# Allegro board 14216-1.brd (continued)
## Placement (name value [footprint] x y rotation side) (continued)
R1202  -  [0R0402-PAD]  121.44 38.15 0 top
R1204  2MR2-GP  [R402H16]  92.28 13.4 90 top
R1205  -  [0R0402-PAD]  87.08 13.06 0 top
R1206  66D5R2F-GP  [R402H16]  92.24 18.05 90 top
R1207  66D5R2F-GP  [R402H16]  92.24 17.22 90 top
R1208  220KR2J-L2-GP  [R402H16]  92.28 14.29 270 top
R1209  66D5R2F-GP  [R402H16]  92.24 16.37 90 top
R1210  66D5R2F-GP  [R402H16]  92.24 15.52 90 top
R1301  -  [0R0402-PAD]  154.92 25.81 0 top
R1302  10KR2J-3-GP  [R402H16]  157.08 26.19 90 top
R1509  100KR2J-1-GP  [R402H16]  144.39 99.94 270 top
R1510  10KR2J-3-GP  [R402H16]  144.22 86.16 270 top
R1511  10KR2J-3-GP  [R402H16]  144.2 85.3 90 top
R1512  10KR2J-3-GP  [R402H16]  146.63 88.89 270 bottom
R1513  10KR2J-3-GP  [R402H16]  144.72 91.51 270 top
R1514  10KR2J-3-GP  [R402H16]  144.72 90.68 90 top
R1515  10KR2J-3-GP  [R402H16]  146.59 89.77 90 bottom
R1601  3KR2F-GP  [R402H16]  120.25 98.2 270 bottom
R1602  22D6R2F-L1-GP  [R402H16]  130.92 78.13 0 top
R1701  10KR2J-3-GP  [R402H16]  166.64 85.82 270 bottom
R1702  1KR2J-1-GP  [R402H16]  141.2 55.03 180 bottom
R1703  1KR2J-1-GP  [R402H16]  146.17 79.25 0 top
R1704  -  [0R0402-PAD]  142.23 56.44 90 bottom
R1705  0R2J-2-GP  [R402H16]  147.11 78.24 0 top
R1706  -  [0R0402-PAD]  140.53 56.44 270 bottom
R1707  -  [0R0402-PAD]  140.38 55.03 180 bottom
R1708  -  [0R0402-PAD]  160.77 67.53 180 bottom
R1709  -  [0R0402-PAD]  192.21 71.65 0 bottom
R1710  0R2J-2-GP  [R402H16]  150.73 83.72 270 bottom
R1713  -  [0R0402-PAD]  149.94 92.16 270 bottom
R1714  8K2R2F-1-GP  [R402H16]  192.22 69.93 180 bottom
R1715  100KR2J-1-GP  [R402H16]  149.83 93.91 90 bottom
R1717  10KR2J-3-GP  [R402H16]  171.04 82.71 270 bottom
R1718  0R2J-2-GP  [R402H16]  142.22 55.04 180 bottom
R1720  330KR2J-L1-GP  [R402H16]  139.84 64.39 0 top
R1721  330KR2J-L1-GP  [R402H16]  138.97 64.39 0 top
R1724  10KR2J-3-GP  [R402H16]  153.37 84.08 270 bottom
R1725  100KR2F-L1-GP  [R402H16]  143.02 53.67 90 bottom
R1726  10KR2J-3-GP  [R402H16]  159.21 49.25 270 bottom
R1727  100KR2J-1-GP  [R402H16]  159.19 48.4 90 bottom
R1728  -  [0R0402-PAD]  159.18 46.69 270 bottom
R1729  0R2J-2-GP  [R402H16]  159.19 47.55 270 bottom
R1801  -  [0R0402-PAD]  133.65 63.77 0 bottom
R1802  1MR2J-1-GP  [R402H16]  124.52 106.63 270 bottom
R1803  3KR2F-GP  [R402H16]  121.52 98.63 0 bottom
R1804  33R2J-2-GP  [R402H16]  129.39 64.42 0 top
R1805  33R2J-2-GP  [R402H16]  127.97 64.39 0 top
R1806  33R2J-2-GP  [R402H16]  144.17 83.04 90 bottom
R1807  -  [0R0402-PAD]  149.25 88.21 90 bottom
R1808  -  [0R0402-PAD]  144.18 83.87 90 bottom
R1809  -  [0R0402-PAD]  144.17 82.15 90 bottom
R1810  -  [0R0402-PAD]  122.82 106.63 90 bottom
R1811  -  [0R0402-PAD]  150.39 86.45 90 bottom
R1812  -  [0R0402-PAD]  143.88 80.48 90 bottom
R1813  0R2J-2-GP  [R402H16]  130.28 64.42 0 top
R1814  1KR2J-1-GP  [R402H16]  143.88 79.59 270 bottom
R1815  1KR2J-1-GP  [R402H16]  149.78 87.34 270 bottom
R1901  1MR2J-1-GP  [R402H16]  140.7 64.39 180 top
R1902  10KR2J-3-GP  [R402H16]  143.8 60.41 180 top
R1903  330KR2J-L1-GP  [R402H16]  140.37 63.12 0 bottom
R1904  -  [0R0402-PAD]  133.07 99.74 270 bottom
R1905  10KR2J-3-GP  [R402H16]  144.71 92.36 270 top
R1906  3KR2F-GP  [R402H16]  132.88 100.85 270 bottom
R1907  33R2J-2-GP  [R402H16]  138.4 64.38 0 bottom
R1908  -  [0R0402-PAD]  132.95 64.42 180 top
R1909  1KR2J-1-GP  [R402H16]  131.17 64.42 180 top
R1911  -  [0R0402-PAD]  139.22 64.38 0 bottom
R1912  33R2J-2-GP  [R402H16]  132.06 64.42 180 top
R1913  330KR2J-L1-GP  [R402H16]  141.21 63.14 0 bottom
R1915  10MR2J-L-GP  [R402H16]  148.62 67.34 180 bottom
R1916  51R2J-2-GP  [R402H16]  91.42 83.38 90 bottom
R1917  51R2J-2-GP  [R402H16]  91.42 80.08 90 bottom
R1918  51R2J-2-GP  [R402H16]  91.42 82.56 90 bottom
R1919  1KR2J-1-GP  [R402H16]  91.42 81.73 90 bottom
R1920  51R2J-2-GP  [R402H16]  91.43 80.9 270 bottom
R2001  -  [0R0402-PAD]  144.87 81.72 270 top
R2002  -  [0R0402-PAD]  144.89 80.87 270 top
R2003  49D9R2F-GP  [R402H16]  131.14 63.76 180 bottom
R2004  -  [0R0402-PAD]  144.28 87.87 270 top
R2005  10KR2J-3-GP  [R402H16]  144.2 85.63 90 bottom
R2006  1KR2J-1-GP  [R402H16]  144.21 88.26 90 bottom
R2007  100KR2J-1-GP  [R402H16]  144.2 87.41 270 bottom
R2008  10KR2J-3-GP  [R402H16]  144.2 84.74 270 bottom
R2009  -  [0R0402-PAD]  150.33 79.65 90 bottom
R2010  10KR2J-3-GP  [R402H16]  143.36 84.24 270 top
R2011  1KR2J-1-GP  [R402H16]  140.2 100.29 180 bottom
R2012  1KR2J-1-GP  [R402H16]  144.44 99.02 270 top
R2013  10KR2J-3-GP  [R402H16]  144.63 83.8 180 top
R2014  1KR2J-1-GP  [R402H16]  150.73 85.5 90 bottom
R2015  10KR2J-3-GP  [R402H16]  150.69 84.51 0 top
R2016  -  [0R0402-PAD]  144.86 82.54 270 top
R2017  -  [0R0402-PAD]  144.26 88.74 270 top
R2018  1KR2J-1-GP  [R402H16]  92.52 95.21 270 bottom
R2019  0R2J-2-GP  [R402H16]  149.96 86.71 0 top
R2020  -  [0R0402-PAD]  146.94 75.88 90 bottom
R2021  0R2J-2-GP  [R402H16]  150.28 81.55 90 top
R2022  -  [0R0402-PAD]  146.94 76.7 90 bottom
R2023  10KR2J-3-GP  [R402H16]  144.43 103.18 270 top
R2024  10KR2J-3-GP  [R402H16]  144.43 102.34 90 top
R2025  10KR2J-3-GP  [R402H16]  149.69 94.77 270 top
R2026  10KR2J-3-GP  [R402H16]  149.68 95.61 90 top
R2027  0R2J-2-GP  [R402H16]  92.51 96.05 90 bottom
R2028  -  [0R0402-PAD]  144.26 87.02 270 top
R2029  -  [0R0402-PAD]  144.26 89.59 270 top
R2030  0R2J-2-GP  [R402H16]  149.26 85.43 90 top
R2031  0R2J-2-GP  [R402H16]  150.7 82.81 0 top
R2032  10KR2J-3-GP  [R402H16]  152.82 79.24 270 bottom
R2033  10KR2J-3-GP  [R402H16]  143.11 103 0 top
R2034  10KR2J-3-GP  [R402H16]  142.22 103 180 top
R2035  10KR2J-3-GP  [R402H16]  148.19 76.33 0 bottom
R2101  -  [0R0402-PAD]  145.4 63.35 270 top
R2102  0R0603-PAD-1-GP-U  [0R0603-PAD-U]  124.51 72.63 90 top
R2103  -  [0R0402-PAD]  147.11 99.29 0 top
R2105  -  [0R0402-PAD]  139.04 106.59 180 bottom
R2108  0R0603-PAD-1-GP-U  [0R0603-PAD-U]  126.92 72.6 90 top
R2110  5D1R2F-GP  [R402H16]  125.08 80.14 270 top
R2112  -  [0R0402-PAD]  146.25 99.3 180 top
R2114  0R5J-5-GP  [R805H24]  146.1 111.36 180 bottom
R2117  -  [0R0402-PAD]  133.48 106.64 90 top
R2118  -  [0R0402-PAD]  127.19 104.6 270 top
R2122  0R0805-PAD-1-GP-U  [0R0805-PAD-U]  140.86 109.18 180 bottom
R2123  0R2J-2-GP  [R402H16]  144.2 86.52 270 bottom
R2401  -  [0R0402-PAD]  195.63 72.16 270 top
R2402  0R0603-PAD-1-GP-U  [0R0603-PAD-U]  180.8 61.9 90 top
R2403  2D2R3-1-U-GP  [R603H22]  183.23 61.49 270 top
R2404  10KR2F-2-GP  [R402H16]  179.12 62.98 270 top
R2405  0R2J-2-GP  [R402H16]  176.11 64.44 180 top
R2406  100KR2F-L1-GP  [R402H16]  178.21 64.9 270 top
R2407  100KR2F-L1-GP  [R402H16]  174.23 64.7 0 top
R2408  -  [0R0402-PAD]  195.42 83.62 270 bottom
R2409  -  [0R0402-PAD]  188.43 74.1 270 bottom
R2410  -  [0R0402-PAD]  189.46 64.92 0 top
R2411  0R2J-2-GP  [R402H16]  190.4 64.92 180 top
R2412  100KR2J-1-GP  [R402H16]  173.42 75.33 90 bottom
R2413  100KR2J-1-GP  [R402H16]  173.21 79.33 90 top
R2414  10KR2J-3-GP  [R402H16]  174.1 76.56 270 top
R2415  10KR2J-3-GP  [R402H16]  194.04 84.68 90 top
R2416  -  [0R0402-PAD]  187.08 70.95 90 bottom
R2417  -  [0R0402-PAD]  194.79 80.88 0 top
R2418  10KR2J-3-GP  [R402H16]  174.6 73.36 180 top
R2419  33R2J-2-GP  [R402H16]  173.31 69.52 90 top
R2420  33R2J-2-GP  [R402H16]  173.31 68.64 90 top
R2421  100KR2J-1-GP  [R402H16]  185.43 66.94 0 bottom
R2422  33R2J-2-GP  [R402H16]  172.93 71.25 90 top
R2423  33R2J-2-GP  [R402H16]  172.93 72.08 90 top
R2424  0R2J-2-GP  [R402H16]  172.9 73.36 0 top
R2425  330KR2J-L1-GP  [R402H16]  173.87 67.8 270 top
R2426  100KR2J-1-GP  [R402H16]  189.86 70.4 180 bottom
R2427  -  [0R0402-PAD]  173.87 66.91 90 top
R2428  -  [0R0402-PAD]  185.7 63.63 0 top
R2429  43R2J-GP  [R402H16]  196.07 67.9 0 top
R2430  -  [0R0402-PAD]  173.21 78.47 90 top
R2431  330KR2J-L1-GP  [R402H16]  169.17 73.38 90 bottom
R2432  1KR2J-1-GP  [R402H16]  171.29 73.81 180 bottom
R2433  20KR2F-L-GP  [R402H16]  170.47 73.81 0 bottom
R2434  0R2J-2-GP  [R402H16]  180.71 60.8 270 top
R2435  -  [0R0402-PAD]  181.6 65.11 270 top
R2436  10KR2J-3-GP  [R402H16]  195.1 75.49 270 top
R2437  0R2J-2-GP  [R402H16]  177.29 85.26 270 bottom
R2438  0R2J-2-GP  [R402H16]  176.48 70.8 0 bottom
R2439  10KR2J-3-GP  [R402H16]  169.88 64.11 180 top
R2440  -  [0R0402-PAD]  176.81 72.59 0 bottom
R2441  -  [0R0402-PAD]  173.16 77.55 270 top
R2442  100KR2J-1-GP  [R402H16]  177.77 71.31 270 bottom
R2443  10KR2J-3-GP  [R402H16]  191.09 66.48 270 bottom
R2444  -  [0R0402-PAD]  194.6 67.8 180 top
R2446  64K9R2F-1-GP  [R402H16]  173.95 66.04 90 top
R2447  100KR2J-1-GP  [R402H16]  195.08 70.78 270 top
R2448  0R2J-2-GP  [R402H16]  188.27 64.67 180 top
R2449  1KR2J-1-GP  [R402H16]  175.39 81.65 180 top
R2450  0R2J-2-GP  [R402H16]  189.87 72.11 180 bottom
R2451  0R2J-2-GP  [R402H16]  184.86 63.63 180 top
R2452  1KR2J-1-GP  [R402H16]  182.06 83 90 bottom
R2453  1KR2J-1-GP  [R402H16]  183.82 82.99 270 bottom
R2501  4K7R2J-2-GP  [R402H16]  156.12 55.02 270 bottom
R2502  1KR2J-1-GP  [R402H16]  33.32 14.73 90 top
R2504  10MR2J-L-GP  [R402H16]  33.32 13.84 90 top
R2601  0R2J-2-GP  [R402H16]  126.42 116.7 270 bottom
R2602  0R2J-2-GP  [R402H16]  128.15 116.68 270 bottom
R2603  18K7R2F-GP  [R402H16]  132.15 115.69 0 bottom
R2604  2KR2F-3-GP  [R402H16]  124.71 116.69 270 bottom
R2605  0R2J-2-GP  [R402H16]  95.31 143.7 270 bottom
R2606  -  [0R0402-PAD]  96.15 140.19 90 bottom
R2607  2KR2F-3-GP  [R402H16]  129.88 116.71 90 bottom
R2608  24K9R2F-L-GP  [R402H16]  133.61 111.5 90 bottom
R2609  24K9R2F-L-GP  [R402H16]  133.62 112.34 90 bottom
R2610  NTC-100K-8-GP  [NTC-603H38]  133.51 114.22 270 bottom
R2611  -  [0R0402-PAD]  182.42 63.54 270 top
R2612  -  [0R0402-PAD]  167.06 64.93 90 top
R2701  -  [0R0402-PAD]  177.23 22.8 270 bottom
R2702  0R0805-PAD-1-GP-U  [0R0805-PAD-U]  176.71 11.06 270 bottom
R2703  0R0603-PAD-1-GP-U  [0R0603-PAD-U]  193.14 19.77 270 bottom
R2704  0R0805-PAD-1-GP-U  [0R0805-PAD-U]  176.7 9.24 270 bottom
R2705  -  [0R0402-PAD]  188.64 9.56 0 bottom
R2706  0R0805-PAD-1-GP-U  [0R0805-PAD-U]  192.34 11.1 270 bottom
R2707  20KR2F-L-GP  [R402H16]  181.59 22.13 0 bottom
R2708  -  [0R0402-PAD]  181.46 13.11 270 top
R2709  200KR2F-L-GP  [R402H16]  180.45 22.13 0 bottom
R2710  0R2J-2-GP  [R402H16]  187.75 9.55 0 bottom
R2711  100KR2J-1-GP  [R402H16]  189.21 19.42 90 bottom
R2712  -  [0R0402-PAD]  183.64 29.62 0 bottom
R2714  -  [0R0402-PAD]  177.48 13.24 270 bottom
R2716  -  [0R0402-PAD]  177.53 14.13 270 bottom
R2717  1KR2J-1-GP  [R402H16]  175.51 21.91 90 bottom
R2718  -  [0R0402-PAD]  176.77 18.77 270 bottom
R2719  -  [0R0402-PAD]  176.36 15.52 270 bottom
R2720  -  [0R0402-PAD]  177.45 16.34 270 bottom
R2722  100KR2J-1-GP  [R402H16]  178.43 21.95 270 bottom
R2901  0R0603-PAD-1-GP-U  [0R0603-PAD-U]  88.6 5.06 90 top
R2902  0R0603-PAD-1-GP-U  [0R0603-PAD-U]  88.48 6.58 90 top
R2903  0R0603-PAD-1-GP-U  [0R0603-PAD-U]  88.48 8.74 90 top
R2904  0R0603-PAD-1-GP-U  [0R0603-PAD-U]  88.48 10.65 90 top
R2906  0R0603-PAD-1-GP-U  [0R0603-PAD-U]  184.26 22.13 270 top
R2907  0R0603-PAD-1-GP-U  [0R0603-PAD-U]  184 28.1 270 top
R2908  10R2F-L-GP  [R402H14]  188.98 15.22 270 bottom
R2909  0R0603-PAD-1-GP-U  [0R0603-PAD-U]  184 26.7 270 top
R2910  10R2F-L-GP  [R402H14]  192.13 15.52 270 bottom
R2911  0R0603-PAD-1-GP-U  [0R0603-PAD-U]  184.26 23.52 270 top
R2912  4K7R2J-2-GP  [R402H16]  189.87 16.11 270 bottom
R2913  4K7R2J-2-GP  [R402H16]  192.13 17.3 270 bottom
R2919  10KR2J-3-GP  [R402H16]  182.23 28.73 180 top
R2920  10KR2J-3-GP  [R402H16]  182.23 27 180 top
R2921  1KR2J-1-GP  [R402H16]  191.58 24.08 270 bottom
R2922  1KR2J-1-GP  [R402H16]  191.54 23.03 270 bottom
R2923  0R0603-PAD-1-GP-U  [0R0603-PAD-U]  180.45 24.29 180 bottom
R3001  0R3J-0-U-GP  [R603H22]  55.52 174.61 180 top
R3003  10KR2J-3-GP  [R402H16]  47.01 162.98 0 top
R3004  10KR2J-3-GP  [R402H16]  53.22 163.06 0 top
R3005  -  [0R0402-PAD]  52.37 163.06 0 top
R3006  0R0603-PAD-1-GP-U  [0R0603-PAD-U]  54.96 172.08 270 top
R3014  1KR2J-1-GP  [R402H16]  54.24 167.85 270 top
R3015  15KR2J-1-GP  [R402H16]  54.24 166.98 90 top
R3016  -  [0R0402-PAD]  58.57 168.07 270 top
R3021  10KR2J-3-GP  [R402H16]  62.7 173.06 90 top
R3022  20KR2J-L2-GP  [R402H16]  62.7 172.18 270 top
R3023  100KR2J-1-GP  [R402H16]  59.07 169.78 270 top
R3032  2K49R2F-GP  [R402H16]  45.07 172.88 90 top
R3033  10KR2J-3-GP  [R402H16]  54.25 168.72 90 top
R3201  33R2J-2-GP  [R402H16]  19.97 19.18 270 bottom
R3202  -  [0R0402-PAD]  15.76 22.59 90 bottom
R3203  6K2R2F-GP  [R402H16]  14 12.5 180 bottom
R3204  -  [0R0402-PAD]  12.18 12.18 0 bottom
R3205  -  [0R0402-PAD]  11.17 12.18 0 bottom
R3301  -  [0R0402-PAD]  29.55 26.3 270 top
R3408  -  [0R0402-PAD]  24.01 40.64 270 bottom
R3409  -  [0R0402-PAD]  24.14 39.62 270 bottom
R3410  -  [0R0402-PAD]  23.3 38.1 270 bottom
R3411  -  [0R0402-PAD]  23.3 37.08 270 bottom
R3501  0R2J-2-GP  [R402H16]  147.92 78.23 180 top
R3601  1KR2J-1-GP  [R402H16]  133.66 143.44 180 top
R3602  200KR2F-L-GP  [R402H16]  162.47 62.72 0 top
R3603  1KR2J-1-GP  [R402H16]  162.49 64.42 180 top
R3605  2K2R2J-2-GP  [R402H16]  164.88 67.59 270 top
R3606  4K7R2J-2-GP  [R402H16]  164.88 66.76 270 top
R3607  100KR2J-1-GP  [R402H16]  28.63 17.66 180 top
R3608  1KR2J-1-GP  [R402H16]  164.88 65.77 270 top
R3609  -  [0R0402-PAD]  39.25 21.49 0 top
R3610  -  [0R0402-PAD]  134.51 143.44 180 top
R3611  -  [0R0402-PAD]  134.1 144.65 270 bottom
R3701  1K8R2F-GP  [R402H16]  59.8 51.85 0 top
R3702  2R2F-GP  [R402H16]  61.96 51.46 270 top
R3703  1K8R2F-GP  [R402H16]  65.01 51.46 270 top
R3704  0R2J-2-GP  [R402H16]  65.01 50.58 90 top
R3705  -  [0R0402-PAD]  66.78 50.7 90 top
R3706  1K8R2F-GP  [R402H16]  66.78 51.59 270 top
R3707  24D9R2F-L-GP  [R402H16]  63.74 51.85 0 top
R3708  2R2F-GP  [R402H16]  65.01 52.35 270 top
R3709  1K8R2F-GP  [R402H16]  61.96 50.58 90 top
R3710  0R2J-2-GP  [R402H16]  59.42 50.45 90 top
R3711  24D9R2F-L-GP  [R402H16]  61.2 53.24 270 top
R3712  0R2J-2-GP  [R402H16]  58.53 51.34 270 top
R3713  2R2F-GP  [R402H16]  58.15 53.7 0 top
R3714  1K8R2F-GP  [R402H16]  59.42 53.24 90 top
R3715  24D9R2F-L-GP  [R402H16]  57.28 53.67 0 top
R3716  1K8R2F-GP  [R402H16]  58.53 52.35 270 top
R3801  0R0805-PAD-1-GP-U  [0R0805-PAD-U]  181.06 71.51 90 bottom
R3802  0R2J-2-GP  [R402H16]  147.46 77.6 270 bottom
R4301  -  [0R0402-PAD]  156.98 174.94 180 top
R4622  2KR2F-3-GP  [R402H16]  118.66 145.83 90 top
R5201  -  [0R0402-PAD]  76.33 164.67 90 bottom
R5202  100KR2J-1-GP  [R402H16]  80.5 154.59 180 bottom
R5203  -  [0R0402-PAD]  85.15 158.25 90 top
R5204  -  [0R0402-PAD]  85.15 157.24 90 top
R5205  33R2J-2-GP  [R402H16]  84.84 155.39 90 top
R5206  -  [0R0402-PAD]  69.32 164.11 90 bottom
R5207  33R2J-2-GP  [R402H16]  81.31 164.44 180 top
R5208  10KR2J-3-GP  [R402H16]  73.79 165.79 0 bottom
R5209  0R2J-2-GP  [R402H16]  74.68 165.79 180 bottom
R5210  100R2J-2-GP  [R402H14]  76.33 165.5 90 bottom
R5211  0R5J-5-GP  [R805H24]  80.42 159.49 180 bottom
R5212  100R2J-2-GP  [R402H14]  84.85 154.55 90 top
R5213  100R2J-2-GP  [R402H14]  85.05 177.31 270 bottom
R5214  0R5J-5-GP  [R805H24]  95.87 154.64 90 bottom
R5215  33R2J-2-GP  [R402H16]  82.19 164.44 180 top
R5216  -  [0R0402-PAD]  84.2 160.88 90 top
R5217  -  [0R0402-PAD]  84.21 160.02 90 top
R5218  100KR2J-1-GP  [R402H16]  81.31 173.51 180 top
R5219  100KR2J-1-GP  [R402H16]  81.31 171.81 0 top
R5222  0R2J-2-GP  [R402H16]  68.03 164.55 180 bottom
R5229  0R5J-5-GP  [R805H24]  85.55 158.53 0 bottom
R5230  0R3J-0-U-GP  [R603H22]  76.05 157 0 bottom
R5231  0R3J-0-U-GP  [R603H22]  77.71 157 0 bottom
R5232  0R3J-0-U-GP  [R603H22]  76.44 160.94 180 bottom
R5401  -  [0R0402-PAD]  21.09 77.96 90 bottom
R5402  -  [0R0402-PAD]  21.09 77.07 90 bottom
R5403  -  [0R0402-PAD]  20.81 75.82 90 bottom
R5404  -  [0R0402-PAD]  20.81 74.99 90 bottom
R5405  -  [0R0402-PAD]  20 68.47 180 bottom
R5406  -  [0R0402-PAD]  20.89 68.47 180 bottom
R5407  -  [0R0402-PAD]  20.76 73.66 90 bottom
R5408  -  [0R0402-PAD]  20.76 72.8 90 bottom
R5409  0R0603-PAD-1-GP-U  [0R0603-PAD-U]  31.93 70.5 90 bottom
R5410  200KR2F-L-GP  [R402H16]  19.82 79.07 270 bottom
R5411  150KR2F-L-GP  [R402H16]  19.82 79.96 270 bottom
R5412  10KR2J-3-GP  [R402H16]  30.69 77.58 270 bottom
R5413  100KR2J-1-GP  [R402H16]  35.05 70.17 270 bottom
R5414  150R2J-L1-GP-U  [R402H16]  19.11 77.47 180 bottom
R5415  150R2J-L1-GP-U  [R402H16]  20.45 66.41 270 bottom
R5416  150R2J-L1-GP-U  [R402H16]  18.8 75.67 180 bottom
R5417  150R2J-L1-GP-U  [R402H16]  18.8 73.94 180 bottom
R5418  0R2J-2-GP  [R402H16]  25.56 79.07 0 top
R5419  -  [0R0402-PAD]  30.69 78.44 90 bottom
R5501  75R2F-2-GP  [R402H16]  23.72 63.9 0 top
R5502  4K7R2J-2-GP  [R402H16]  28.32 59.09 180 bottom
R5503  0R3J-0-U-GP  [R603H22]  23.52 67.37 90 top
R5504  0R3J-0-U-GP  [R603H22]  30.59 59.06 90 top
R5505  12KR2F-L-GP  [R402H16]  31.37 64.77 0 bottom
R5507  33R2J-2-GP  [R402H16]  26.45 68.83 180 top
R5508  4K7R2J-2-GP  [R402H16]  29.67 61.31 180 bottom
R5509  4K7R2J-2-GP  [R402H16]  29.67 59.06 180 bottom
R5510  100KR2J-1-GP  [R402H16]  31.17 68.49 180 top
R5511  33R2J-2-GP  [R402H16]  25.59 68.84 180 top
R5512  4K7R2J-2-GP  [R402H16]  28.84 61.31 180 bottom
R5513  75R2F-2-GP  [R402H16]  23.69 61.64 0 top
R5514  75R2F-2-GP  [R402H16]  23.63 58.92 0 top
R5515  4K7R2J-2-GP  [R402H16]  30.5 59.06 180 bottom
R5516  4K7R2J-2-GP  [R402H16]  30.51 61.31 180 bottom
R5517  0R2J-2-GP  [R402H16]  32.01 68.48 180 top
R5601  0R0805-PAD-1-GP-U  [0R0805-PAD-U]  191.68 38.97 180 bottom
R5602  0R2J-2-GP  [R402H16]  153.58 88.2 0 bottom
R5603  0R5J-5-GP  [R805H24]  158.92 78.98 90 bottom
R5604  10KR2J-3-GP  [R402H16]  151.52 90.05 180 top
R5605  -  [0R0402-PAD]  148.78 96.6 270 bottom
R5607  100KR2J-1-GP  [R402H16]  162.62 73.46 90 bottom
R5801  -  [0R0402-PAD]  158.78 63.28 0 bottom
R5802  -  [0R0402-PAD]  159.79 63.28 0 bottom
R5803  -  [0R0402-PAD]  163.05 53.07 180 top
R5804  -  [0R0402-PAD]  177.9 53.65 0 top
R5805  -  [0R0402-PAD]  178.73 53.65 0 top
R5806  0R2J-2-GP  [R402H16]  177.42 55.7 270 top
R5807  -  [0R0402-PAD]  177.01 53.65 0 top
R5808  -  [0R0402-PAD]  158.69 55.21 0 bottom
R5809  0R0805-PAD-1-GP-U  [0R0805-PAD-U]  166.73 38.44 180 top
R5810  0R2J-2-GP  [R402H16]  169.45 38.49 180 top
R5811  -  [0R0402-PAD]  159.68 55.21 0 bottom
R6102  100R2J-2-GP  [R402H14]  191.19 173.35 90 top
R6103  470R2J-2-GP  [R402H16]  30.18 4.54 90 top
R6104  -  [0R0402-PAD]  36 9.2 270 top
R6105  -  [0R0402-PAD]  32.72 9.2 270 top
R6106  0R2J-2-GP  [R402H16]  44.18 3.71 270 top
R6107  330R2J-3-GP  [R402H16]  33.98 4.53 90 top
R6108  330R2J-3-GP  [R402H16]  37.83 3.71 270 top
R6109  100R2J-2-GP  [R402H14]  191.58 176.34 180 top
R6110  10KR2J-3-GP  [R402H16]  42.76 8.71 270 top
R6201  1KR2J-1-GP  [R402H16]  194.61 117.39 270 top
R6202  -  [0R0402-PAD]  196.47 112.79 270 top
R6203  10KR2J-3-GP  [R402H16]  59.9 75.87 180 bottom
R6204  0R2J-2-GP  [R402H16]  47.4 74.31 90 top
R6205  0R3J-0-U-GP  [R603H22]  186.11 122.44 90 top
R6206  51KR2J-1-GP  [R402H16]  186.92 123.93 180 top
R6207  100KR2J-1-GP  [R402H16]  186.03 123.93 180 top
R6208  100KR2J-1-GP  [R402H16]  189.97 127.72 0 top
R6209  4K7R2J-2-GP  [R402H16]  58.52 71.79 0 top
R6210  0R2J-2-GP  [R402H16]  47.4 73.47 90 top
R6211  100R3J-4-GP  [R603H22]  48.15 69.88 270 top
R6212  0R3J-0-U-GP  [R603H22]  50.42 79.12 0 top
R6213  0R3J-0-U-GP  [R603H22]  48.19 75.93 90 top
R6214  20KR2F-L-GP  [R402H16]  45.08 79.16 90 top
R6215  0R2J-2-GP  [R402H16]  47.41 77.46 0 bottom
R6216  -  [0R0402-PAD]  43.68 79.85 270 bottom
R6217  0R2J-2-GP  [R402H16]  48.25 77.46 0 bottom
R6301  0R2J-2-GP  [R402H16]  187.89 35.11 90 top
R6302  0R2J-2-GP  [R402H16]  187.89 31.04 90 top
R6305  0R3J-0-U-GP  [R603H22]  192.28 12.67 270 bottom
R6501  0R2J-2-GP  [R402H16]  169.78 35.41 90 bottom
R6502  0R2J-2-GP  [R402H16]  168.49 35.84 180 bottom
R7301  2K49R2F-GP  [R402H16]  151.6 150 90 bottom
R7302  10KR2F-2-GP  [R402H16]  151.72 142.5 90 bottom
R7303  10KR2J-3-GP  [R402H16]  148.41 130.26 90 bottom
R7304  0R2J-2-GP  [R402H16]  151.36 121.76 180 bottom
R7305  0R2J-2-GP  [R402H16]  151.39 126.84 270 bottom
R7306  100KR2F-L1-GP  [R402H16]  152.22 121.76 0 bottom
R7307  200R2F-L-GP  [R402H16]  152.13 144.3 180 bottom
R7308  0R2J-2-GP  [R402H16]  157.52 125.2 90 bottom
R7312  10KR2J-3-GP  [R402H16]  158.8 125.64 180 bottom
R7313  0R2J-2-GP  [R402H16]  190.51 126.1 180 bottom
R7501  60D4R2F-GP  [R402H16]  171.94 145.65 270 top
R7503  60D4R2F-GP  [R402H16]  169.58 146.49 270 top
R7505  40D2R2F-GP  [R402H16]  175.63 146.06 0 top
R7506  51D1R2F-GP  [R402H16]  177.94 151.84 270 top
R7507  42D2R2F-GP  [R402H16]  176.49 148.24 270 top
R7508  10KR2F-2-GP  [R402H16]  183.39 161.58 90 bottom
R7509  10KR2F-2-GP  [R402H16]  151.75 163.61 270 top
R7510  10KR2F-2-GP  [R402H16]  199.19 142.27 180 bottom
R7511  10KR2F-2-GP  [R402H16]  166.13 164.04 180 bottom
R7512  10KR2F-2-GP  [R402H16]  198.3 142.27 180 bottom
R7518  10KR2J-3-GP  [R402H16]  171.25 130.32 180 top
R7519  0R2J-2-GP  [R402H16]  172.64 129.92 90 top
R7601  10KR2J-3-GP  [R402H16]  193.79 129.05 90 bottom
R7602  10KR2J-3-GP  [R402H16]  172.53 139.51 180 top
R7603  1MR2J-1-GP  [R402H16]  180.19 129.44 180 bottom
R7604  1K3R2J-GP  [R402H16]  180.19 127.66 0 bottom
R7605  100KR2J-1-GP  [R402H16]  174.02 128.47 270 top
R7606  10KR2J-3-GP  [R402H16]  174.86 130.08 180 top
R7607  40K2R2F-GP  [R402H16]  171.94 133 90 top
R7608  4K99R2F-L-GP  [R402H16]  187.43 130 90 top
R7609  10KR2J-3-GP  [R402H16]  170.42 123.91 90 bottom
R7610  100KR2J-1-GP  [R402H16]  188.53 129.47 180 bottom
R7611  4K99R2F-L-GP  [R402H16]  192.38 128.56 0 bottom
R7612  10KR2J-3-GP  [R402H16]  196.99 123.95 180 bottom
R7613  10KR2J-3-GP  [R402H16]  191.4 126.1 0 bottom
R7614  10KR2F-2-GP  [R402H16]  187.43 129.19 270 top
R7615  10KR2J-3-GP  [R402H16]  171.69 123.68 0 bottom
R7616  20KR2F-L-GP  [R402H16]  191.12 129.57 180 top
R7617  10KR2J-3-GP  [R402H16]  172.77 137.22 90 top
R7618  10KR2F-2-GP  [R402H16]  190.3 129.57 0 top
R7619  34K8R2F-1-GP  [R402H16]  191.55 128.56 0 bottom
R7620  10KR2F-2-GP  [R402H16]  194.13 127.74 180 bottom
R7621  10KR2J-3-GP  [R402H16]  173.86 125.53 180 bottom
R7622  10KR2J-3-GP  [R402H16]  173.77 124.27 270 bottom
R7623  0R2J-2-GP  [R402H16]  195.54 129.98 90 bottom
R7624  -  [0R0402-PAD]  200.26 136.79 90 top
R7625  10KR2J-3-GP  [R402H16]  175.59 125.53 0 bottom
R7626  10KR2J-3-GP  [R402H16]  180.58 129.7 90 top
R7627  10KR2J-3-GP  [R402H16]  195.51 129.12 270 bottom
R7628  10KR2J-3-GP  [R402H16]  175.5 137.45 0 top
R7629  0R2J-2-GP  [R402H16]  186.67 127.16 180 bottom
R7630  0R2J-2-GP  [R402H16]  176.64 130.08 0 top
R7631  10KR2J-3-GP  [R402H16]  175.75 130.08 180 top
R7632  10KR2J-3-GP  [R402H16]  176.86 125.33 270 bottom
R7633  10KR2J-3-GP  [R402H16]  179.18 125.43 270 bottom
R7634  10KR2J-3-GP  [R402H16]  176 124.16 270 bottom
R7635  10KR2J-3-GP  [R402H16]  172.5 123.68 0 bottom
R7636  0R2J-2-GP  [R402H16]  180.47 124.59 180 bottom
R7637  10KR2J-3-GP  [R402H16]  174.73 131.86 180 top
R7638  30K1R2F-L-GP  [R402H16]  193.56 129.57 180 top
R7639  24K9R2F-L-GP  [R402H16]  192.74 129.57 180 top
R7640  4K99R2F-L-GP  [R402H16]  191.93 129.57 180 top
R7642  30K1R2F-L-GP  [R402H16]  190.35 129.44 180 bottom
R7643  10KR2J-3-GP  [R402H16]  187.56 127.16 180 bottom
R7644  10KR2J-3-GP  [R402H16]  181.36 124.59 0 bottom
R7645  10KR2J-3-GP  [R402H16]  188.45 127.16 0 bottom
R7646  45K3R2F-L-GP  [R402H16]  174.75 125.53 0 bottom
R7647  34K8R2F-1-GP  [R402H16]  173.77 123.45 270 bottom
R7648  10KR2J-3-GP  [R402H16]  145.87 130.65 180 top
R7649  10KR2J-3-GP  [R402H16]  182.66 124.88 270 bottom
R7650  4K99R2F-L-GP  [R402H16]  170.42 124.72 90 bottom
R7652  -  [0R0402-PAD]  187.64 129.47 0 bottom
R7653  -  [0R0402-PAD]  193.82 122.1 270 bottom
R7654  45K3R2F-L-GP  [R402H16]  176.87 126.17 270 bottom
R7655  45K3R2F-L-GP  [R402H16]  189.47 129.44 180 bottom
R7806  1K33R2F-GP  [R402H16]  198.3 134.96 90 bottom
R7807  1K33R2F-GP  [R402H16]  198.31 133.2 270 bottom
R7808  243R2F-2-GP  [R402H16]  193.02 129.98 90 bottom
R7809  243R2F-2-GP  [R402H16]  186.54 143.86 90 bottom
R7810  162R2F-GP  [R402H16]  188.37 143.9 270 top
R7903  1K33R2F-GP  [R402H16]  152.18 165.81 0 top
R7904  1K33R2F-GP  [R402H16]  180.83 165.64 270 bottom
R7912  243R2F-2-GP  [R402H16]  180.83 164.75 90 bottom
R7913  243R2F-2-GP  [R402H16]  166.22 162.34 180 bottom
R7914  162R2F-GP  [R402H16]  166.25 162.25 0 top
R8001  243R2F-2-GP  [R402H16]  189.95 158.28 0 top
R8002  243R2F-2-GP  [R402H16]  186.65 143.89 270 top
R8101  243R2F-2-GP  [R402H16]  151.75 164.49 90 top
R8102  243R2F-2-GP  [R402H16]  166.26 160.54 180 top
R8301  100KR2J-1-GP  [R402H16]  145.83 128.91 0 top
R8302  10KR2J-3-GP  [R402H16]  144.37 132.27 270 top
R8303  0R2J-2-GP  [R402H16]  142.68 132.28 270 top
R8304  0R5J-5-GP  [R805H24]  182.89 124.47 270 top
R8305  1MR2J-1-GP  [R402H16]  166.86 57.05 180 top
R8312  0R2J-2-GP  [R402H16]  168.15 56.32 270 top
R8313  0R2J-2-GP  [R402H16]  142.96 138.6 90 top
R8314  220KR2J-L2-GP  [R402H16]  171.53 56.37 270 top
R8315  0R2J-2-GP  [R402H16]  179.18 124.54 270 bottom
R9601  1KR2J-1-GP  [R402H16]  100.52 100.27 270 top
R9602  0R2J-2-GP  [R402H16]  149.86 95.71 270 bottom
R9603  0R2J-2-GP  [R402H16]  187.71 69.5 180 bottom
R9604  0R2J-2-GP  [R402H16]  90.02 88.93 270 bottom
R9605  0R2J-2-GP  [R402H16]  171.01 84.46 270 bottom
RJ45  RJ45-8P-184-GP  [C100PF-10809-L]  6.4 170.97 90 bottom
RN401  SRN51J-1-GP  [ARES8-CN24H22]  88.24 90.92 270 bottom
RN1501  SRN2K2J-1-GP  [ARES2H16]  135.26 99.89 0 bottom
RN1503  SRN10KJ-5-GP  [ARES2H18]  150.19 89.87 270 bottom
RN1505  SRN10KJ-6-GP  [ARES8-CN24-MUH20]  144.56 97.08 270 bottom
RN1601  SRN10KJ-6-GP  [ARES8-CN24-MUH20]  153.45 76.2 270 bottom
RN1701  SRN10KJ-5-GP  [ARES2H18]  168.86 82.46 180 top
RN1702  SRN0J-6-GP  [SMD-ARES4H20]  162.73 67.59 270 bottom
RN1703  SRN10KJ-5-GP  [ARES2H18]  141.16 57.99 90 bottom
RN1801  SRN10KJ-6-GP  [ARES8-CN24-MUH20]  144.54 93.4 270 bottom
RN1803  SRN10KJ-5-GP  [ARES2H18]  112.36 99.5 0 bottom
RN1804  SRN10KJ-5-GP  [ARES2H18]  137.5 63.71 0 top
RN1806  SRN0J-7-GP-U  [ARES8-CN24H22]  135.46 63.58 0 bottom
RN1807  SRN2K2J-4-GP  [ARES8-CN24-UH20]  158.99 72.46 90 bottom
RN1809  SRN10KJ-6-GP  [ARES8-CN24-MUH20]  151.11 81.82 270 bottom
RN1810  SRN10KJ-5-GP  [ARES2H18]  161.78 70.39 0 bottom
RN1811  SRN2K2J-1-GP  [ARES2H16]  158.03 69.23 270 bottom
RN1901  SRN20KJ-1-GP  [SMD-ARES4H20]  142.36 62.44 0 top
RN1902  SRN10KJ-6-GP  [ARES8-CN24-MUH20]  144.34 90.49 90 bottom
RN2002  SRN10KJ-6-GP  [ARES8-CN24-MUH20]  144.57 94.2 90 top
RN2006  SRN10KJ-5-GP  [ARES2H18]  166.79 81.66 180 top
RN2007  SRN10KJ-5-GP  [ARES2H18]  141.73 101.06 180 bottom
RN2008  SRN2K2J-1-GP  [ARES2H16]  143.76 101.06 180 bottom
RN2011  SRN10KJ-6-GP  [ARES8-CN24-MUH20]  144.57 97.12 90 top
RN2012  SRN10KJ-6-GP  [ARES8-CN24-MUH20]  153.48 82.25 90 bottom
RN2401  SRN4K7J-8-GP  [SMD-ARES4H18]  174.21 85.11 180 bottom
RN2501  SRN4K7J-8-GP  [SMD-ARES4H18]  150.45 55.66 270 bottom
RN2602  SRN2K2J-1-GP  [ARES2H16]  126.98 118.83 270 top
RN2701  -  [0R4P2R-PAD]  176.17 27.74 270 bottom
RN2901  SRN2K2J-1-GP  [ARES2H16]  181.13 22.72 270 top
RN3001  SRN10KJ-5-GP  [ARES2H18]  58.05 162.98 270 top
RN3101  SRN75J-1-GP  [ARES8-CN24H22]  21.7 177.58 180 bottom
RN4301  SRN100J-4-GP  [ARES8-CN24H20]  161.99 175.08 90 top
RN4401  SRN4K7J-8-GP  [SMD-ARES4H18]  101.98 160.91 90 bottom
RN5201  SRN100J-4-GP  [ARES8-CN24H20]  76.18 167.34 270 bottom
RN5203  SRN100KJ-5-GP  [ARES8-CN24H20]  71.66 167.34 90 bottom
RN5401  SRN2K2J-1-GP  [ARES2H16]  36.99 78.92 90 bottom
RN5402  SRN470J-3-GP  [ARES8-CN24H20]  24.37 72.67 90 top
RN5403  SRN470J-3-GP  [ARES8-CN24H20]  24.37 76.61 90 top
RN5404  -  [0R4P2R-PAD]  38.46 75.41 270 bottom
RN5405  -  [0R4P2R-PAD]  38.46 73.36 270 bottom
RN5501  SRN2K2J-1-GP  [ARES2H16]  28.56 70.49 0 top
RN6201  SRN10KJ-5-GP  [ARES2H18]  52.64 77.75 270 top
RN6202  SRN33J-5-GP-U  [SMD-ARES4H18]  56.7 77.64 270 top
RN6203  SRN33J-5-GP-U  [SMD-ARES4H18]  49.82 73.88 90 top
RN6204  SRN2K2J-1-GP  [ARES2H16]  56.65 74.17 180 top
RN6501  SRN0J-7-GP-U  [ARES8-CN24H22]  172.02 36.04 0 bottom
RN7401  SRN10KJ-5-GP  [ARES2H18]  163.93 131.67 0 top
RN7402  SRN10KJ-5-GP  [ARES2H18]  161.9 131.67 0 top
RN7403  SRN10KJ-5-GP  [ARES2H18]  170.67 134.9 90 top
RN7404  SRN10KJ-5-GP  [ARES2H18]  165.96 131.67 0 top
RN7501  SRN100J-3-GP  [SMD-ARES4H18]  190.85 167.6 180 bottom
RN7502  SRN100J-3-GP  [SMD-ARES4H18]  190.62 164.31 90 bottom
RN7503  SRN100J-3-GP  [SMD-ARES4H18]  180.73 165.51 0 top
RN7504  SRN100J-3-GP  [SMD-ARES4H18]  180.71 159.13 0 top
RN7505  SRN100J-3-GP  [SMD-ARES4H18]  185.83 166.27 0 top
RN7506  SRN100J-3-GP  [SMD-ARES4H18]  188.79 167.61 180 bottom
RN7507  SRN100J-3-GP  [SMD-ARES4H18]  187.84 167.08 0 top
RN7508  SRN100J-3-GP  [SMD-ARES4H18]  190.4 166.54 270 top
RN7509  SRN100J-3-GP  [SMD-ARES4H18]  190.4 168.56 270 top
RN7510  SRN100J-3-GP  [SMD-ARES4H18]  190.7 162.27 90 bottom
RN7511  SRN100J-3-GP  [SMD-ARES4H18]  182.76 164.19 0 top
RN7512  SRN100J-3-GP  [SMD-ARES4H18]  183.45 169.39 0 top
RN7513  SRN100J-3-GP  [SMD-ARES4H18]  187.97 158.44 270 top
RN7514  SRN100J-3-GP  [SMD-ARES4H18]  187.97 160.47 270 top
RN7515  SRN100J-3-GP  [SMD-ARES4H18]  180.74 162.44 0 top
RN7516  SRN100J-3-GP  [SMD-ARES4H18]  181.41 169.39 0 top
RN7517  SRN100J-3-GP  [SMD-ARES4H18]  185.8 169.35 0 top
RN7518  SRN100J-3-GP  [SMD-ARES4H18]  190.42 162.48 270 top
RN7519  SRN100J-3-GP  [SMD-ARES4H18]  191.04 160.47 270 top
RN7520  SRN100J-3-GP  [SMD-ARES4H18]  186.69 167.6 180 bottom
RN7521  SRN100J-3-GP  [SMD-ARES4H18]  190.42 164.49 270 top
RN7522  SRN100J-3-GP  [SMD-ARES4H18]  183.28 166.73 90 top
RN7601  SRN4K7J-8-GP  [SMD-ARES4H18]  199.37 135.28 270 top
RN7602  SRN10KJ-5-GP  [ARES2H18]  150.86 130.84 90 bottom
RN7603  SRN2K2J-1-GP  [ARES2H16]  180.45 126.39 0 top
RN7604  SRN2K2J-1-GP  [ARES2H16]  199.37 133.13 90 top
RN7605  SRN2K2J-1-GP  [ARES2H16]  178.42 126.39 0 top
RN9601  SRN0J-6-GP  [SMD-ARES4H20]  163.81 70.39 180 bottom
RTC1  BAT-060003HA002M213ZL-GP-U1  [060003HA002M213ZL-U2]  41.3 14.77 180 bottom
SPI25  W25Q64FVSSIQ-GP  [SOIC8-1H86]  152.13 51.29 270 bottom
SPK1  ACES-CON4-29-GP  [50224-0040N-001]  72.1 7.22 270 bottom
SPR1  SPRING-31-GP  [SPR7345H154]  85.3 59.27 270 top
SPR2  SPRING-24-GP-U  [SPR5230H134]  69.8 77.57 0 bottom
SPR3  SPRING-13-GP-U  [SPR7837H229]  134.3 35.02 90 bottom
TC1201  ST330U2VDM-4-GP-U  [CT7343H83]  73.26 40.92 270 top
TC3501  SC100U6D3V6MX-GP  [C1206H71]  21.57 42.31 0 top
THM26  NCT7718W-GP  [MSOP8-1H44]  128.38 114.2 90 bottom
TP402  TPAD14-OP-GP  [TPAD14-OP]  95.07 89.15 180 bottom
TP403  TPAD14-OP-GP  [TPAD14-OP]  94.37 97.41 180 bottom
TP501  TPAD14-OP-GP  [TPAD14-OP]  117.41 76.91 0 top
TP503  TPAD14-OP-GP  [TPAD14-OP]  118.39 78.74 0 top
TP601  TPAD14-OP-GP  [TPAD14-OP]  95.05 72.98 180 bottom
TP602  TPAD14-OP-GP  [TPAD14-OP]  97.9 72.55 0 top
TP603  TPAD14-OP-GP  [TPAD14-OP]  98.1 94.94 0 top
TP604  TPAD14-OP-GP  [TPAD14-OP]  98.06 96.91 0 top
TP605  TPAD14-OP-GP  [TPAD14-OP]  110.65 95.71 0 top
TP606  TPAD14-OP-GP  [TPAD14-OP]  106.92 96.8 0 top
TP607  TPAD14-OP-GP  [TPAD14-OP]  106.92 94.9 0 top
TP608  TPAD14-OP-GP  [TPAD14-OP]  98.35 89.02 0 top
TP619  TPAD14-OP-GP  [TPAD14-OP]  125.94 86.62 0 top
TP620  TPAD14-OP-GP  [TPAD14-OP]  126.91 87.51 0 top
TP701  TPAD14-OP-GP  [TPAD14-OP]  99.8 98.58 180 bottom
TP702  TPAD14-OP-GP  [TPAD14-OP]  102.11 87.09 0 top
TP703  TPAD14-OP-GP  [TPAD14-OP]  101.39 86.03 0 top
TP704  TPAD14-OP-GP  [TPAD14-OP]  102.07 88.33 0 top
TP705  TPAD14-OP-GP  [TPAD14-OP]  100.32 86.92 0 top
TP801  TPAD14-OP-GP  [TPAD14-OP]  111.31 96.83 0 top
TP1501  TPAD14-OP-GP  [TPAD14-OP]  135.39 82.11 0 top
TP1601  TPAD14-OP-GP  [TPAD14-OP]  131.88 76.61 0 top
TP1602  TPAD14-OP-GP  [TPAD14-OP]  131.88 74.73 0 top
TP1702  TPAD14-OP-GP  [TPAD14-OP]  137.01 80.29 0 top
TP1703  TPAD14-OP-GP  [TPAD14-OP]  135.39 76.21 0 top
TP1704  TPAD14-OP-GP  [TPAD14-OP]  135.23 79.1 0 top
TP1705  TPAD14-OP-GP  [TPAD14-OP]  133.03 77.89 0 top
TP1706  TPAD14-OP-GP  [TPAD14-OP]  140.52 80.32 180 bottom
TP1707  TPAD14-OP-GP  [TPAD14-OP]  133.73 80.17 0 top
TP1801  TPAD14-OP-GP  [TPAD14-OP]  140.89 81.49 180 bottom
TP1802  TPAD14-OP-GP  [TPAD14-OP]  142.09 82.8 180 bottom
TP1803  TPAD14-OP-GP  [TPAD14-OP]  141.72 80.59 180 bottom
TP1901  TPAD14-OP-GP  [TPAD14-OP]  96.88 71.78 0 top
TP1902  TPAD14-OP-GP  [TPAD14-OP]  137.38 64.89 180 bottom
TP2002  TPAD14-OP-GP  [TPAD14-OP]  138.92 76.99 0 top
TP2003  TPAD14-OP-GP  [TPAD14-OP]  135.7 91.43 0 top
TP2101  TPAD14-OP-GP  [TPAD14-OP]  127.72 86.59 0 top
TP2102  TPAD14-OP-GP  [TPAD14-OP]  127.86 85.16 0 top
TP2103  TPAD14-OP-GP  [TPAD14-OP]  127.13 89.35 0 top
TP2104  TPAD14-OP-GP  [TPAD14-OP]  125.76 87.96 0 top
TP2105  TPAD14-OP-GP  [TPAD14-OP]  129.05 85.76 0 top
TP2106  TPAD14-OP-GP  [TPAD14-OP]  133.05 82.1 0 top
TP2107  TPAD14-OP-GP  [TPAD14-OP]  130.15 89.42 0 top
TP2108  TPAD14-OP-GP  [TPAD14-OP]  129.3 78.4 0 top
TP2109  TPAD14-OP-GP  [TPAD14-OP]  132.29 83.06 0 top
TP2201  TPAD14-OP-GP  [TPAD14-OP]  97.29 67.62 180 bottom
TP2202  TPAD14-OP-GP  [TPAD14-OP]  138.23 99.27 180 bottom
TP2203  TPAD14-OP-GP  [TPAD14-OP]  94.22 98.66 180 bottom
TP2204  TPAD14-OP-GP  [TPAD14-OP]  140.02 98.41 180 bottom
TP2205  TPAD14-OP-GP  [TPAD14-OP]  98.07 98.25 0 top
TP2206  TPAD14-OP-GP  [TPAD14-OP]  140.53 73.51 180 bottom
TP2207  TPAD14-OP-GP  [TPAD14-OP]  140.5 72.25 180 bottom
TP2208  TPAD14-OP-GP  [TPAD14-OP]  95.94 69.09 180 bottom
TP2702  TPAD14-OP-GP  [TPAD14-OP]  179.56 12.73 270 top
TP3001  TPAD14-OP-GP  [TPAD14-OP]  51.74 177.3 0 top
TP3002  TPAD14-OP-GP  [TPAD14-OP]  50.9 178.2 180 top
TP3003  TPAD14-OP-GP  [TPAD14-OP]  49.96 172.65 180 top
TP3201  TPAD14-OP-GP  [TPAD14-OP]  19.77 16.83 180 bottom
TP5801  TPAD14-OP-GP  [TPAD14-OP]  159.57 52.13 0 top
TP5802  TPAD14-OP-GP  [TPAD14-OP]  168.41 51.19 0 top
TP5803  TPAD14-OP-GP  [TPAD14-OP]  167.13 51.17 0 top
TP5804  TPAD14-OP-GP  [TPAD14-OP]  165.75 51.17 0 top
TP7503  TPAD14-OP-GP  [TPAD14-OP]  172.55 144.61 0 top
TP7504  TPAD14-OP-GP  [TPAD14-OP]  170.8 152.43 0 top
TP7601  TPAD14-OP-GP  [TPAD14-OP]  155.56 133.15 0 top
TP7602  TPAD14-OP-GP  [TPAD14-OP]  158.1 134.52 0 top
TP7603  TPAD14-OP-GP  [TPAD14-OP]  177.75 137.21 0 top
TP7604  TPAD14-OP-GP  [TPAD14-OP]  176.53 137.2 0 top
TP7605  TPAD14-OP-GP  [TPAD14-OP]  157.21 133.38 0 top
TP7606  TPAD14-OP-GP  [TPAD14-OP]  189.47 125.63 180 bottom
TP9601  TPAD14-OP-GP  [TPAD14-OP]  96.91 89.67 0 top
TP9602  TPAD14-OP-GP  [TPAD14-OP]  97.54 90.94 0 top
TP9611  TPAD14-OP-GP  [TPAD14-OP]  89.97 91.78 180 bottom
TP9612  TPAD14-OP-GP  [TPAD14-OP]  96.27 90.94 0 top
TP9613  TPAD14-OP-GP  [TPAD14-OP]  99.95 91.2 0 top
TP9614  TPAD14-OP-GP  [TPAD14-OP]  93.73 90.05 180 bottom
TP9615  TPAD14-OP-GP  [TPAD14-OP]  95.1 90.38 180 bottom
TP9616  TPAD14-OP-GP  [TPAD14-OP]  101.53 90.4 0 top
TP9617  TPAD14-OP-GP  [TPAD14-OP]  92.46 90.05 180 bottom
TP9618  TPAD14-OP-GP  [TPAD14-OP]  100.26 89.64 0 top
TP9619  TPAD14-OP-GP  [TPAD14-OP]  98.86 90.15 0 top
TP9620  TPAD14-OP-GP  [TPAD14-OP]  96.4 82.69 0 top
TP9621  TPAD14-OP-GP  [TPAD14-OP]  101.33 92.49 0 top
TP9622  TPAD14-OP-GP  [TPAD14-OP]  93.93 84.38 180 bottom
TP9623  TPAD14-OP-GP  [TPAD14-OP]  91.83 91.32 180 bottom
TP9624  TPAD14-OP-GP  [TPAD14-OP]  89.98 90.46 180 bottom
TP9626  TPAD14-OP-GP  [TPAD14-OP]  101.22 83.7 0 top
TP9627  TPAD14-OP-GP  [TPAD14-OP]  97.67 82.69 0 top
TP9628  TPAD14-OP-GP  [TPAD14-OP]  96.69 84.61 0 top
TP9629  TPAD14-OP-GP  [TPAD14-OP]  99.95 83.78 0 top
TP9630  TPAD14-OP-GP  [TPAD14-OP]  98.68 83.58 0 top
TP9631  TPAD14-OP-GP  [TPAD14-OP]  97.98 84.73 0 top
TP9632  TPAD14-OP-GP  [TPAD14-OP]  94.51 85.97 0 top
TP9633  TPAD14-OP-GP  [TPAD14-OP]  93.58 84.9 0 top
TP9634  TPAD14-OP-GP  [TPAD14-OP]  95.21 83.19 0 top
TP9635  TPAD14-OP-GP  [TPAD14-OP]  94.02 83.56 0 top
TP9636  TPAD14-OP-GP  [TPAD14-OP]  95.2 84.92 0 top
TP9637  TPAD14-OP-GP  [TPAD14-OP]  100.47 85.12 0 top
TP9638  TPAD14-OP-GP  [TPAD14-OP]  95.76 86.03 0 top
TP9639  TPAD14-OP-GP  [TPAD14-OP]  97.01 86.08 0 top
TP9640  TPAD14-OP-GP  [TPAD14-OP]  96.14 87.89 0 top
TP9641  TPAD14-OP-GP  [TPAD14-OP]  99.31 85.49 0 top
TP9642  TPAD14-OP-GP  [TPAD14-OP]  97.41 87.89 0 top
TP9643  TPAD14-OP-GP  [TPAD14-OP]  94.87 87.89 0 top
TP9644  TPAD14-OP-GP  [TPAD14-OP]  171.43 85.55 0 bottom
TP9645  TPAD14-OP-GP  [TPAD14-OP]  186.52 68.78 180 bottom
TP9646  TPAD14-OP-GP  [TPAD14-OP]  167.19 73.41 180 bottom
TP9647  TPAD14-OP-GP  [TPAD14-OP]  91.17 90.07 180 bottom
TP9648  TPAD14-OP-GP  [TPAD14-OP]  99.97 101.59 0 top
TP9649  TPAD14-OP-GP  [TPAD14-OP]  165.97 73.5 180 bottom
TP9650  TPAD14-OP-GP  [TPAD14-OP]  98.42 93.75 0 top
TP9651  TPAD14-OP-GP  [TPAD14-OP]  114 99.97 180 bottom
TP9652  TPAD14-OP-GP  [TPAD14-OP]  114.03 98.74 180 bottom
TP9653  TPAD14-OP-GP  [TPAD14-OP]  140.43 82.97 180 bottom
TP9654  TPAD14-OP-GP  [TPAD14-OP]  147.53 95.69 180 bottom
TPAD1  ACES-CON8-40-GP  [50505-0084N-002]  66.3 77.27 90 top
TR3404  FILTER-4P-137-GP  [L125100-4P-1H28]  21.93 35 0 top
TR3405  FILTER-4P-137-GP  [L125100-4P-1H28]  183.96 40.67 180 bottom
TR3406  FILTER-4P-137-GP  [L125100-4P-1H28]  183.33 36.88 180 bottom
U701  74LVC1G07GW-GP  [SC70-5H44]  100.24 96.96 180 top
U2101  SLG59M1470VTR-GP  [DFN9J2015H32]  143.43 111.74 270 bottom
U3201  RTS5170-GR-GP  [QFN24-G2D5H40-U]  16.03 17.58 270 bottom
U3402  AZ1045-04F-R7G-GP  [DFN10G2510H26]  19.26 39.68 270 bottom
U3504  AP22802BW5-7-GP  [SOT-23-5H58]  26.27 45.34 90 bottom
U3505  AP22802BW5-7-GP  [SOT-23-5H58]  198.69 19.08 0 bottom
U3601  AP22966DC8-7-GP  [SON14J3020-G2610H32]  39.28 17.94 0 top
U3801  SY6288C10CAC-GP  [MSOP8-1H44]  181.52 68.5 270 bottom
U5201  RT9724GB-GP  [SOT-23-5H51]  83.29 154.97 90 bottom
U5502  RTD2168-CGT-GP  [QFN32-G3D6H40]  28.39 63.83 0 top
U5504  CAT24C128WI-GT3-GP  [SOIC8H69]  28.25 51.9 180 bottom
U5601  TPS2001CDGNR-GP  [MSOP8-1G189157H43]  159.84 75.97 270 bottom
U7301  U74LVC1G08G-AL5-R-GP-U  [SC70-5-1H44]  149.37 122.94 0 bottom
U8301  AP22966DC8-7-GP  [SON14J3020-G2610H32]  147.43 137.32 90 top
USB1  SKT-USB13-111-GP  [SKT-USB13-160166-2]  5.27 39.97 90 bottom
VRAM1  MT41K256M16HA-107G-E-GP  [BGA96D0914H48]  188.4 136.92 270 bottom
VRAM2  MT41K256M16HA-107G-E-GP  [BGA96D0914H48]  188.4 150.91 270 bottom
VRAM3  MT41K256M16HA-107G-E-GP  [BGA96D0914H48]  173.2 162.37 0 bottom
VRAM4  MT41K256M16HA-107G-E-GP  [BGA96D0914H48]  159.2 162.37 0 bottom
VRAM5  MT41K256M16HA-107G-E-GP  [BGA96D0914H48]  188.4 136.92 90 top
VRAM6  MT41K256M16HA-107G-E-GP  [BGA96D0914H48]  188.4 150.91 90 top
VRAM7  MT41K256M16HA-107G-E-GP  [BGA96D0914H48]  173.2 162.37 180 top
VRAM8  MT41K256M16HA-107G-E-GP  [BGA96D0914H48]  159.2 162.37 180 top
WLAN1  SKT-MINI67P-3-GP-U1  [2199230-7]  168.6 53.77 90 bottom
X1801  XTAL-24MHZ-81-GP  [OSC-3225-4P-4H36]  124.26 109.94 0 bottom
X1901  XTAL-32D768KHZ-65-GP  [SMD49-6914-0403H56]  154.63 66.26 0 bottom
X3001  XTAL-25MHZ-181-GP  [OSC-3225-4P-4H36]  47.83 176.61 180 top
X7601  XTAL-27MHZ-85-GP-U  [OSC-3225-4P-4H30]  183.88 128.55 0 bottom
XF3101  XFORM-12P-48-GP  [XFORM12A127097H91]  24.21 168.94 90 bottom
XF3102  XFORM-12P-48-GP  [XFORM12A127097H91]  24.21 168.94 270 top

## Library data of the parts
AFTP2501 AFTP2502 AFTP2801-AFTP2803 AFTP2901-AFTP2904 AFTP3101-AFTP3108 AFTP3301-AFTP3310 AFTP3401-AFTP3403 AFTP3801-AFTP3803 AFTP3805 AFTP3806 AFTP3901-AFTP3910 AFTP5501-AFTP5508 AFTP5601 AFTP5801-AFTP5807 AFTP6101-AFTP6104 AFTP6201-AFTP6203 AFTP6206-AFTP6208 AFTP6213-AFTP6243 AFTP6245-AFTP6248 AFTP6301-AFTP6307 AFTP6309-AFTP6311 AFTP6313 AFTP6314 = AFTE14P-75: tolerance: ZZ.AFT14.101
BATT1 = 200277MR008G121ZR-U: tolerance: 20.81153.008
C701 C3512 C3513 C3515 C7326 C7518 C7520 C7710 C7717 PC4717-PC4737 PC4739-PC4742 PC4744 PC4923-PC4928 = C805H58: tolerance: 78.22610.51L
C702 C1120 C1121 C1201-C1204 C1206 C1210 C1211 C1217 C1218 C1220-C1222 C1301 C1302 C1306 C1308-C1311 C1314 C1316 C1317 C1319 C1320 C2110 C2136 C2147 C2401-C2404 C2406-C2410 C2412 C2414 C2417 C2502 C2602 C2605 C2608-C2610 C2612 C2707 C2709 C2710 C2717 C2719 C2720 C3002 C3003 C3007-C3009 C3013 C3017 C3019 C3021-C3025 C3202 C3205 C3301 C3405 C3406 C3504 C3507 C3517 C3604 C5201 C5401 C5501 C5503 C5517 C5520 C5522 C5524 C5604 C5606 C5801-C5804 C6201-C6204 C7318 C7501 C7502 C7505 C7506 C7508-C7510 C7512 C7522-C7524 C7529 C7532-C7534 C7601 C7602 C7605 C7729 C7734 C7735 C7804 C7820 C7821 C7827 C7829-C7836 C7909 C7910 C7912 C7913 C7921-C7923 C7925 C7927-C7930 C8001 C8002 C8004 C8005 C8010-C8013 C8017-C8020 C8101 C8102 C8104 C8105 C8110-C8113 C8117-C8120 C8303 C8306 C8308 C8309 C8311 C9602 EC401 EC402 EC701 EC702 EC1707 EC1902 EC1903 EC2601 EC2708 EC2709 EC6104 EC6105 EC6207 EC6208 PC4517 PC4518 PC4601 PC4606 PC4610 PC4708 PC4709 PC4824 PC4903 PC4906 PC4915 PC4921 PC5102 PC8201 = C402H22: tolerance: 78.10421.2FL
C703 C1101-C1103 C1105 C1109 C1111 C1113 C1116-C1118 C1122 C1212-C1216 C1303 C1304 C1307 C1312 C1313 C1901 C1902 C2104 C2105 C2109 C2114 C2116 C2128 C2135 C2137 C2138 C2416 C2418 C2703 C2704 C3015 C3018 C3201 C3206 C3508 C3510 C3518 C3801 C3802 C5206 C7312 C7319 C7711-C7714 C7728 C7736 C8302 C8304 EC9718-EC9738 PC4815 PC5119 PC5120 = C402H22: tolerance: 78.10523.5FL
C1001-C1003 C1209 C1315 C2123 C2601 C2712 C2713 C2901 C3605 C5502 C5521 C5523 C5805 C5806 C7323 C7604 PC4916 PC4917 PC8303 PC8307 = C603H38: tolerance: 78.10610.5BL
C1004-C1006 C1104 C1106-C1108 C1110 C1112 C1114 C1115 C1119 C1123-C1125 C1207 C1208 C1318 C1321 C2142 C2501 C3303 C3603 C5601 C5605 C5609 C5610 C7517 C8307 C8310 = C805H54: tolerance: 78.10623.51L
C1017-C1020 C2411 C2705 C7606 = C402H22: tolerance: 78.22510.5FL
C1205 C1305 C2405 C2413 C5504 = C603H36: tolerance: 78.22523.5BL
C1601-C1612 C3014 C3016 C3403 C3404 C5203 C5209-C5213 C5402-C5409 C5525-C5530 = C402H22: tolerance: 78.10421.2FL; signal model: C402H22_SCD1U16V2KX-3GP
C1701 C2415 EC6102 EC6103 = C402H22: tolerance: 78.22124.2FL
C1801 C1802 C1903 C1904 C3001 C3011 C7607 C7608 EC4305 = C402H22: tolerance: 78.15034.1FL
C2101 C2503 = C402H22: tolerance: 78.47420.5FL
C2141 C2604 C2611 C2701 C2702 C2706 C2708 C2711 C2715 C2716 C2718 C2907 C2908 C3004 C3005 C3010 C3012 C3203 C3302 C5204 C5207 C7310 C7315 C7317 C7324 C7513 C7514 C7603 C7701-C7704 C7708 C7709 C7719-C7726 C7730-C7732 PC4526 PC4920 = C603H36: tolerance: 78.47520.5BL
C2421 PC8205 PC8217 PC8219 PC8222 = C402H22: tolerance: 78.47034.1FL
C2422 C2613 C5511 C5516 EC2905-EC2908 = C402H22: tolerance: 78.10134.1FL
C2603 C2607 C8316 EC4401 = C402H22: tolerance: 78.22224.2FL
C2606 = C603H36: tolerance: 78.47134.1BL
C2723 EC5206 = C402H22: tolerance: 78.22034.1FL
C3101 = C1808H56: tolerance: 78.1013N.1AL
C3106 C3204 C8301 PC4203-PC4205 PC4412 PC4425 PC4531 PC4902 PC8204 PC8302 = C402H22: tolerance: 78.10324.2FL
C3601 C3602 C8305 = C402H22: tolerance: 78.47124.2FL
C3701-C3703 = C402H22: tolerance: 78.22321.2FL
C5202 EC1501 EC1502 EC1702-EC1706 EC2704-EC2707 EC2901-EC2904 EC6101 EC9702 EC9708-EC9711 EC9714-EC9717 EC9739-EC9741 EC9743-EC9745 EC9747 EC9748 PC4521 PC4609 PC4612 PC4613 PC4821 PC8203 = C402H22: tolerance: 78.10224.2FL
C5205 EC4304 EC4601 PC4202 PC4409 PC4419 PC4514-PC4516 PC4525 PC4530 PC4532 PC4534 PC4535 PC4704 PC4822 PC4825 PC4913 PC4919 PC8207 PC8211 PC8216 = C603H36: tolerance: 78.10424.2BL
C5208 C5214 EC1801 EC1901 EC2503 EC2602 EC2701 EC3101-EC3108 EC3201 EC4301 EC4302 = C402H22: tolerance: 78.10034.1FL
C5506 C5509 C5512 EC1701 EC2501 EC2502 EC3301-EC3307 = C402H22: tolerance: 78.4R7B4.1FL
C5507 C5513 PC4522 PC4523 PC4823 = C402H22: tolerance: 78.18034.1FL
C5510 C5514 C5518 = C402H22: tolerance: 78.3R374.1FL
C5519 = C402H22: tolerance: 78.10321.2FL
C5602 C5603 C5607 C5608 C5611 C5612 C5615 C5616 = C402H22: tolerance: 78.10324.2FL; signal model: C402H22_SCD01U50V2KX-1GP
C7301-C7308 = C402H22: tolerance: 78.22423.5FL; signal model: C402H22_SCD22U10V2KX-1GP
C7316 EC2703 EC4202 EC4303 EC4402 EC4701 EC9701 EC9703-EC9707 EC9712 EC9713 EC9742 EC9746 EC9749-EC9761 PC4402 PC4420 PC4421 PC4423 PC4424 PC4710 PC8202 PC8220 PC8221 PC8225 PC8226 = C402H22: tolerance: 78.10422.5FL
C7507 C7525 C7805 C7810-C7812 C7814 C7816 C7817 C7822 C7906 C7911 C7915-C7917 C7919 C7924 C7926 C8003 C8006-C8009 C8014-C8016 C8103 C8106-C8109 C8114-C8116 PC4524 PC4904 = C603H36: tolerance: 78.10520.2BL
C7609 C7610 = C402H22: tolerance: 78.27224.2FL
C7803 C7902 = C402H22: tolerance: 78.82124.2FL
CARD1 = CS1S-461HN: tolerance: 20.I0147.001
CN6301 = 196547-24031-3: tolerance: 020.K0139.0024
CPU1 = BGA1168M4024H64: tolerance: 71.HASWE.G0U
D2001 = SOD323AKH38: tolerance: 83.R2004.G8F
D2401 = SOD323AKH40: tolerance: 83.R2004.H8F
D2501 = SOT-23-9H44: tolerance: 75.00040.07D
D2601 D5501 = SOD323AKH38: tolerance: 83.R5003.H8H
D2701 D5201 D5202 D8301 = SOT23-2D4-312H48: tolerance: 75.00054.E7D
D3602 = SOT23-2D4-312H44: tolerance: 83.00016.K11
D4301-D4303 PD4203 = SOT23-2D4-312H44: tolerance: 75.00099.O7D
D5401 = SOT-23-9H44: tolerance: 83.00056.Q11
D7301 = SOT23-2D4-312H44: tolerance: 75.00054.X7D
D7601 D7602 = SOD723AKH27: tolerance: 83.00400.C1F
DB1 = PAD-10P-177042: tolerance: ZZ.00PAD.Y41
DCIN1 = 50458-00601-W01: tolerance: 20.F2132.006
DM1 = 80001-1921: tolerance: 62.10017.X41
DM2 = AS0A621-J4SB-7H: tolerance: 62.10024.S11
EC4201 PC4206 PC4406 PC4415-PC4418 PC4426 PC4519 PC4527 PC4528 PC4701-PC4703 PC4826 PC4912 PC8210 PC8214 PC8215 PC8224 = C805H56: tolerance: 78.10622.51L
EC5205 = C402H22: tolerance: 78.6R864.1FL
EC5210 EC5801 EC5802 EC6201-EC6206 = C402H22: tolerance: 78.33034.1FL
ED6101 = SOD882-10D6-1H20: tolerance: 83.05725.0A0
EL4201-EL4204 R1101 R1105 R2122 R2702 R2704 R2706 R3801 R5601 R5809 = 0R0805-PAD-U: tolerance: ZZ.R0805.001
EU401 = TVS10D6-D3D5-1H13: tolerance: 083.00105.00AF
EU3101 EU3102 = DFN10G2510H26: tolerance: 75.01004.073
EU3403 EU3404 = SOT-6H58: tolerance: 75.09904.07C
EU5602 U3402 = DFN10G2510H26: tolerance: 75.01045.073
F5201 = POLYSW-4633-UH63: tolerance: 69.60040.001
F5203 F6201 = POLYSW-2114H50: tolerance: 69.50007.921
F5501 = POLYSW-2114H30: tolerance: 69.48001.081
FAN1 = 3703K-Q03N-11L: tolerance: 20.F1841.003
FAN261 = SOIC8H69: tolerance: 74.02113.0E1
G1901 G6101 G6102 = CON2O-U: tolerance: ZZ.CON2O.XXX
GPU1 = BGA595M23H83: tolerance: 71.0N14M.B0U
H1 H6 = HOLE256R126: tolerance: ZZ.00PAD.Z61
H2-H5 = HOLE335R115: tolerance: ZZ.00PAD.D01
H7 = HOLE296R182: tolerance: ZZ.00PAD.Y51
HCPU1-HCPU3 = HOLE197R166: tolerance: ZZ.00PAD.V71
HDA27 = QFN48J6-G465H40: tolerance: 71.03234.003
HDD1 = 132F12-010000-A2-R: tolerance: 020.K0125.0012
HDLED1 = LED3015-1A2K-3PH44: tolerance: 83.01221.R70
HDMI1 = PAD-D-SUB-HDMI-COLAY-U: tolerance: ZZ.00PAD.BI1
HGPU1-HGPU3 = STF237R117H81: tolerance: 34.44L12.001
KB1 = FL4S030HT6R300-DT: tolerance: 20.K0592.030
KB_BL1 = 51575-00401-W01: tolerance: 20.K0800.004
KBC24 = LQFP128H63: tolerance: 071.00285.000G
L1101 L1102 PR4409 R3001 R5230-R5232 R5503 R5504 R6205 R6212 R6213 R6305 = R603H22: tolerance: 63.00000.00L
L1103 L1104 = L603H40: tolerance: 68.2R21D.10R
L3001 = L2520-D820H41: tolerance: 68.4R71E.10G
L5501-L5503 = L1608-UH38: tolerance: 68.00084.A11; signal model: L1608-UH38_BLM18BB220SN-GP
L7301 = L603H38: tolerance: 68.00335.151
L7501 L7601 = L603H38: tolerance: 68.00335.051
L7602 = L603H38: tolerance: 68.00909.261
LCD1 = 51540-04001-W01: tolerance: 20.K0678.040
LED1 = LED3020-3P-6H44: tolerance: 83.01222.X80
LOM30 = QFN32J4-G2D85H36: tolerance: 71.08111.U03
ODD1 = 51519-02001-W03: tolerance: 20.K0708.020
PC4010 = C603H36: tolerance: 78.47422.5BL
PC4201 PC4403 PC4404 PC4407 PC4427 PC4431 PC4434 PC4533 PC4604 PC4901 = C603H36: tolerance: 78.10522.5BL
PC4401 PC4536 PC4838 = C603: tolerance: 78.56124.2BL
PC4408 PC4509 PC4529 PC4814 PC4909 PC4911 PC4914 PC8208 PC8209 PC8212 PC8213 = C805H54: tolerance: 78.47522.51L
PC4411 PC4707 = C402H22: tolerance: 78.47322.2FL
PC4413 = C603H36: tolerance: 78.33224.2BL
PC4422 = C402H22: tolerance: 78.22134.1FL
PC4433 = C402H22: tolerance: 78.47420.8FL
PC4520 = C603: tolerance: 78.33124.2BL
PC4611 = C402H22: tolerance: 78.68224.2FL
PC4706 = C603H40: tolerance: 78.22422.2BL
PC4918 = C402H22: tolerance: 78.22423.5FL
PC4922 PC8206 PC8218 = C402H22: tolerance: 78.33124.2FL
PC8223 = C402-TO0D2H23: tolerance: 78.56224.2FL
PD4201 = D5436AKH97: tolerance: 83.P6SBM.DAG
PD4204 = SOT-23-10H44: tolerance: 83.0024V.0A1
PD4302 = SOD123FLAKH40: tolerance: 83.SMF18.0AH
PD4401 = SOD323AKH42: tolerance: 83.1R504.A8F
PD4404 = SOD323AKH42: tolerance: 83.04148.D1H
PD4501 = SOD323AKH42: tolerance: 83.15R03.C3F
PD4502 PD4503 = SOT-23-13H51: tolerance: 75.00054.C7D
PG4402-PG4405 PG4407-PG4411 PG4530 PG4532 PG4535 PG4701 PG4702 PG4832 PG4907 = GAP-CLOSE-PWR-3: tolerance: ZZ.CLOSE.001
PG4412-PG4415 PG4517-PG4529 PG4531 PG4533 PG4534 PG4536-PG4538 PG4540-PG4545 PG4703-PG4708 PG4824-PG4828 PG4830 PG4831 PG4834 PG4837 PG4838 PG4901-PG4906 PG4908-PG4920 PG5105 PG8201-PG8212 PG8312-PG8315 = GAP-CLOSE-PWR: tolerance: ZZ.CON2d.XXX
PL4401 = L686647H119: tolerance: 68.5R610.10U
PL4501 PL4801 = L736630-MH119: tolerance: 68.2R210.20B
PL4502 = L736630H119: tolerance: 68.3R310.20A
PL4701 = L115100-275300H158: tolerance: 68.R2210.10C
PL4902 = L736630H119: tolerance: 68.R6810.20B
PL8201 PL8202 = L736630H119: tolerance: 68.R3310.201
PQ4201 Q1201 = SOT23DGS2D4H48: tolerance: 84.05067.031
PQ4202 Q2603 Q3002 Q3003 Q5401 = SOT23CBE2D4H44: tolerance: 84.T3904.H11
PQ4204 = SOT323CBE2D2H44: tolerance: 84.00124.H1K
PQ4205 = SOT323CBE2D2H44: tolerance: 84.00124.K1K
PQ4206 PQ8306 PQ8307 Q1202 Q1901 Q2401 Q2403 Q2505 Q2602 Q3001 Q5403 Q6103 Q6105 Q6205 Q7301 Q7606 Q8301 = SOT23DGS2D4H44: tolerance: 84.2N702.J31
PQ4401 PQ4402 PQ4408 PQ4410 PQ8304 PQ8305 Q1701 Q1801 Q2601 Q3601 Q6204 Q7601 Q7602 = SOT-363H44: tolerance: 84.2N702.A3F
PQ4409 Q2404 = SOT23CBE2D4H44: tolerance: 84.T3906.E11
PQ4414 = SOT23DGS2D4H44: tolerance: 84.2N702.031
PQ8308 = PPAK-5PH45: tolerance: 84.SRA06.037
PR4202 PR4617 = R402H16: tolerance: 64.15025.6DL
PR4203 PR8258 PR8259 R405 R706 R710 R1302 R1510-R1515 R1701 R1717 R1724 R1726 R1902 R1905 R2005 R2008 R2010 R2013 R2015 R2023-R2026 R2032-R2035 R2414 R2415 R2418 R2436 R2439 R2443 R2919 R2920 R3003 R3004 R3021 R3033 R5208 R5412 R5604 R6110 R6203 R7303 R7312 R7518 R7601 R7602 R7606 R7609 R7612 R7613 R7615 R7617 R7621 R7622 R7625-R7628 R7631-R7635 R7637 R7643-R7645 R7648 R7649 R8302 = R402H16: tolerance: 63.10334.1DL
PR4204 R3605 = R402H16: tolerance: 63.22234.1DL
